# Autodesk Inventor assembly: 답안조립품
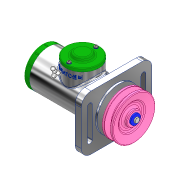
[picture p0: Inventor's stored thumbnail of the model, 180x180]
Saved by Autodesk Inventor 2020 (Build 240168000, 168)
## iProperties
Created: 2021-07
Part Number: 답안조립품
Document SubType Name: Assembly
Designer: MIRAE
Author: MIRAE
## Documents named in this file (20)
- C:\Users\MIRAE\Desktop\710706V1023\답안조립품.iam
- C:\Users\MIRAE\Desktop\710706V1023\본체.ipt
- C:\Users\MIRAE\Desktop\710706V1023\V-벨트풀리.ipt
- C:\Users\MIRAE\Desktop\710706V1023\너트 M10.ipt
- C:\Users\MIRAE\Desktop\710706V1023\멈춤링 15 x 1.ipt
- C:\Users\MIRAE\Desktop\710706V1023\멈춤링 35 x 1.6.ipt
- C:\Users\MIRAE\Desktop\710706V1023\베어링 15 x 35 x 11.ipt
- C:\Users\MIRAE\Desktop\710706V1023\볼트 M4 x 10.ipt
- C:\Users\MIRAE\Desktop\710706V1023\부시1.ipt
- C:\Users\MIRAE\Desktop\710706V1023\부시2.ipt
- C:\Users\MIRAE\Desktop\710706V1023\사이드 커버.ipt
- 사이드 커버.ipt
- C:\Users\MIRAE\Desktop\710706V1023\십자볼트 M3 x 10.ipt
- C:\Users\MIRAE\Desktop\710706V1023\오일 실 15 25 7.ipt
- C:\Users\MIRAE\Desktop\710706V1023\와셔 3 x 6.ipt
- C:\Users\MIRAE\Desktop\710706V1023\와셔 4 x 16.ipt
- C:\Users\MIRAE\Desktop\710706V1023\와셔 10 x 21.ipt
- C:\Users\MIRAE\Desktop\710706V1023\축.ipt
- C:\Users\MIRAE\Desktop\710706V1023\키 4 x 4 x 18.ipt
- C:\Users\MIRAE\Desktop\710706V1023\탑 커버.ipt
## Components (2 placed, 2 different names)
1. V-벨트풀리:1 — 각도:3
2. ISO 4017 M4 x 10:1
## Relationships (1: Angle 1)
- 각도:3 [Angle]: V-벨트풀리:1
